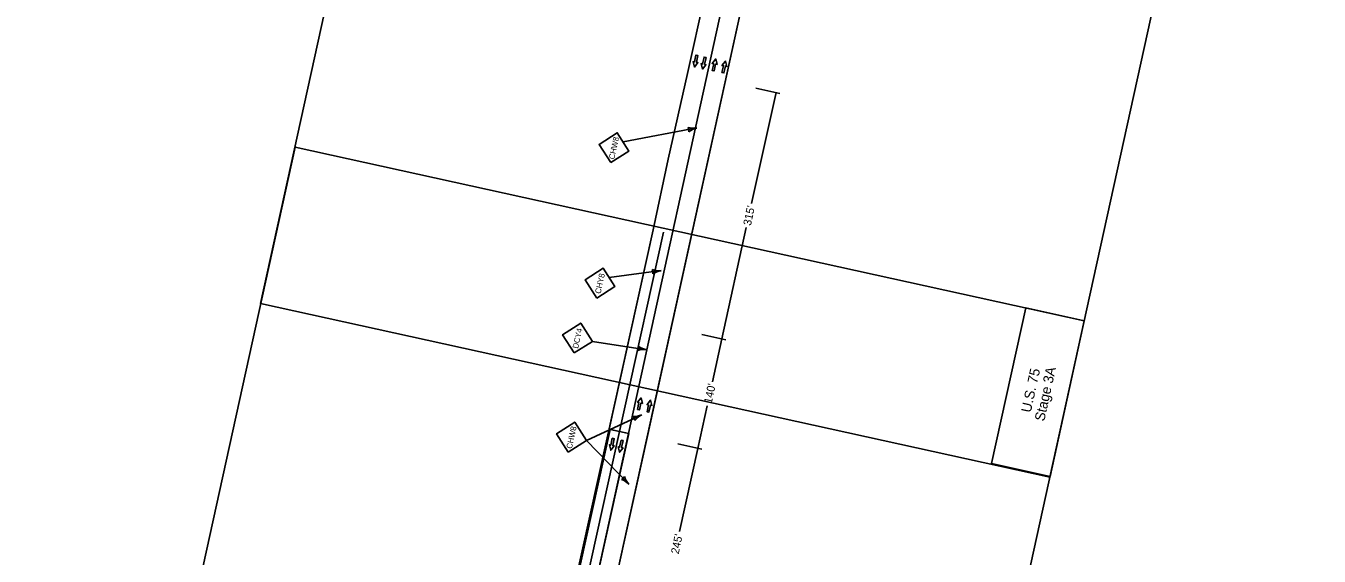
# Model space of a CAD drawing. Extents: x 14104283 to 14129344, y 8637090 to 8673339.
# Drawn here: x 14106925 to 14108541, y 8638327 to 8638989 of the extents above; entities that cross this region are included whole.
import ezdxf

# ---------------------------------------------------------------- set-up
doc = ezdxf.new("R2010")
doc.units = 0
for name, color, linetype in [('Cell', 7, 'Continuous'), ('Default', 7, 'Continuous'), ('dsnNonPlotable', 7, 'Continuous'), ('dsnPaintExistingBrokenLaneLineWhite', 7, 'Continuous'), ('dsnPaintExistingDoubleCenterYellow', 7, 'Continuous'), ('dsnPaintExistingEdgeLineRightWhite', 7, 'Continuous'), ('dsnStdLabel', 7, 'Continuous'), ('dsnTextOverlapOdd', 7, 'Continuous'), ('EdgePaved', 7, 'Continuous')]:
    doc.layers.add(name, color=color, linetype=linetype)

msp = doc.modelspace()

# ---------------------------------------------------------------- linework, layer by layer
at = {"layer": 'Cell'}
for points in [[(14107762.5, 8638952.7), (14107764.9, 8638952.2), (14107763.1, 8638943.7), (14107764.9, 8638943.3), (14107760.5, 8638937.8), (14107758.8, 8638944.6), (14107760.6, 8638944.2)], [(14107772.6, 8638950.2), (14107775.1, 8638949.7), (14107773.2, 8638941.1), (14107775, 8638940.7), (14107770.7, 8638935.3), (14107768.9, 8638942.1), (14107770.8, 8638941.7)], [(14107785.1, 8638933), (14107782.7, 8638933.5), (14107784.6, 8638942), (14107782.7, 8638942.4), (14107787.1, 8638947.9), (14107788.8, 8638941.1), (14107787, 8638941.5)], [(14107797.4, 8638930.4), (14107795, 8638931), (14107796.9, 8638939.5), (14107795, 8638939.9), (14107799.4, 8638945.3), (14107801.1, 8638938.6), (14107799.3, 8638939)], [(14107691.8, 8638509.5), (14107689.4, 8638510.1), (14107691.2, 8638518.6), (14107689.4, 8638519), (14107693.8, 8638524.5), (14107695.5, 8638517.7), (14107693.7, 8638518.1)], [(14107703.7, 8638506.8), (14107701.3, 8638507.3), (14107703.1, 8638515.8), (14107701.3, 8638516.2), (14107705.7, 8638521.7), (14107707.4, 8638514.9), (14107705.6, 8638515.3)], [(14107657.9, 8638474.1), (14107660.4, 8638473.5), (14107658.5, 8638465), (14107660.3, 8638464.6), (14107655.9, 8638459.1), (14107654.2, 8638465.9), (14107656, 8638465.5)], [(14107669, 8638471.6), (14107671.4, 8638471.1), (14107669.5, 8638462.5), (14107671.4, 8638462.1), (14107667, 8638456.7), (14107665.3, 8638463.5), (14107667.1, 8638463.1)]]:
    msp.add_lwpolyline(points, close=True, dxfattribs=at)
for points in [[(14107760.6, 8638944.2), (14107758.8, 8638944.6), (14107760.5, 8638937.8), (14107764.9, 8638943.3), (14107763.1, 8638943.7), (14107764.9, 8638952.2), (14107762.5, 8638952.7), (14107760.6, 8638944.2)], [(14107770.8, 8638941.7), (14107768.9, 8638942.1), (14107770.7, 8638935.3), (14107775, 8638940.7), (14107773.2, 8638941.1), (14107775.1, 8638949.7), (14107772.6, 8638950.2), (14107770.8, 8638941.7)], [(14107787, 8638941.5), (14107788.8, 8638941.1), (14107787.1, 8638947.9), (14107782.7, 8638942.4), (14107784.6, 8638942), (14107782.7, 8638933.5), (14107785.1, 8638933), (14107787, 8638941.5)], [(14107799.3, 8638939), (14107801.1, 8638938.6), (14107799.4, 8638945.3), (14107795, 8638939.9), (14107796.9, 8638939.5), (14107795, 8638931), (14107797.4, 8638930.4), (14107799.3, 8638939)], [(14107693.7, 8638518.1), (14107695.5, 8638517.7), (14107693.8, 8638524.5), (14107689.4, 8638519), (14107691.2, 8638518.6), (14107689.4, 8638510.1), (14107691.8, 8638509.5), (14107693.7, 8638518.1)], [(14107705.6, 8638515.3), (14107707.4, 8638514.9), (14107705.7, 8638521.7), (14107701.3, 8638516.2), (14107703.1, 8638515.8), (14107701.3, 8638507.3), (14107703.7, 8638506.8), (14107705.6, 8638515.3)], [(14107656, 8638465.5), (14107654.2, 8638465.9), (14107655.9, 8638459.1), (14107660.3, 8638464.6), (14107658.5, 8638465), (14107660.4, 8638473.5), (14107657.9, 8638474.1), (14107656, 8638465.5)], [(14107667.1, 8638463.1), (14107665.3, 8638463.5), (14107667, 8638456.7), (14107671.4, 8638462.1), (14107669.5, 8638462.5), (14107671.4, 8638471.1), (14107669, 8638471.6), (14107667.1, 8638463.1)]]:
    msp.add_lwpolyline(points, dxfattribs=at)
at = {"layer": 'Default'}
for p, q in [((14107678, 8638480.1), (14107872.9, 8639367.3)), ((14107896.3, 8639362.1), (14107701.4, 8638474.9)), ((14107781.5, 8639063.2), (14107752, 8638929.7)), ((14107678, 8638480.1), (14107804.9, 8639058.1)), ((14107708.9, 8638734.4), (14107653.9, 8638485.4)), ((14107625.5, 8638241.2), (14107678, 8638480.1)), ((14107653.9, 8638485.4), (14107678, 8638480.1)), ((14107701.4, 8638474.9), (14107648.9, 8638236.1))]:
    msp.add_line(p, q, dxfattribs=at)
msp.add_lwpolyline([(14107752, 8638929.7), (14107727.7, 8638822.9), (14107708.9, 8638734.4)], dxfattribs=at)
msp.add_lwpolyline([(14107392.9, 8637186.7), (14107369.5, 8637191.9), (14107655.1, 8638485.1), (14107678.5, 8638480)], close=True, dxfattribs=at)
at = {"layer": 'dsnNonPlotable'}
for points in [[(14107218.4, 8638642.3), (14107554.8, 8640173.3), (14108541.3, 8639956.6), (14108204.9, 8638425.6)], [(14106925, 8637306.7), (14107261.4, 8638837.7), (14108247.8, 8638620.9), (14107911.4, 8637089.9)]]:
    msp.add_lwpolyline(points, close=True, dxfattribs=at)
at = {"layer": 'dsnPaintExistingBrokenLaneLineWhite'}
msp.add_line((14107381.2, 8637189.3), (14107721.8, 8638731.5), dxfattribs=at)
at = {"layer": 'dsnPaintExistingDoubleCenterYellow'}
msp.add_line((14107435.8, 8637377.6), (14107678, 8638480.1), dxfattribs=at)
at = {"layer": 'dsnPaintExistingEdgeLineRightWhite'}
for p, q in [((14107781.7, 8639064), (14107752, 8638929.7)), ((14107468.8, 8637416), (14107828.5, 8639053.6)), ((14107708.9, 8638734.4), (14107415.9, 8637407.6))]:
    msp.add_line(p, q, dxfattribs=at)
msp.add_lwpolyline([(14107752, 8638929.7), (14107727.7, 8638822.9), (14107708.9, 8638734.4)], dxfattribs=at)
at = {"layer": 'dsnStdLabel'}
for p, q in [((14107832, 8638767.2), (14107862.5, 8638905.9)), ((14107867.4, 8638904.8), (14107837.3, 8638911.4)), ((14107671.3, 8638844.3), (14107763.6, 8638861.7)), ((14107794.9, 8638598.2), (14107825.4, 8638737.2)), ((14107653.9, 8638675.1), (14107719.1, 8638683.5)), ((14107633.1, 8638595.1), (14107700.8, 8638584.7)), ((14107799.8, 8638597.1), (14107769.7, 8638603.7)), ((14107783.1, 8638544.5), (14107794.9, 8638598.2)), ((14107764.9, 8638461.4), (14107776.5, 8638514.6)), ((14107625.5, 8638471.5), (14107694.7, 8638503.4)), ((14107625.5, 8638471.5), (14107678.6, 8638416.6)), ((14107769.8, 8638460.4), (14107739.6, 8638467)), ((14107742, 8638357.5), (14107764.9, 8638461.4))]:
    msp.add_line(p, q, dxfattribs=at)
for points in [[(14107655.9, 8638818.4), (14107678.6, 8638832.9), (14107664.1, 8638855.7), (14107641.3, 8638841.1)], [(14107638.4, 8638649.1), (14107661.1, 8638663.7), (14107646.6, 8638686.4), (14107623.9, 8638671.9)], [(14107610.3, 8638580.6), (14107633.1, 8638595.1), (14107618.5, 8638617.9), (14107595.8, 8638603.3)], [(14107602.8, 8638456.9), (14107625.5, 8638471.5), (14107611, 8638494.2), (14107588.2, 8638479.7)]]:
    msp.add_lwpolyline(points, close=True, dxfattribs=at)
for centre, radius, start, end in [((14107759.4, 8638884.2), 22.9, 252.5977, 280.669), ((14107744.7, 8638858.1), 8.86, 352.9347, 28.4031), ((14107767.9, 8638839.1), 22.9, 100.6688, 128.7401), ((14107716, 8638706.2), 22.9, 249.1268, 277.1981), ((14107699.8, 8638681), 8.86, 349.4638, 24.9322), ((14107721.8, 8638660.6), 22.9, 97.1979, 125.2692), ((14107681.8, 8638587.7), 8.86, 333.54, 9.0085), ((14107697.3, 8638562.1), 22.9, 81.2742, 109.3455), ((14107704.3, 8638607.4), 22.9, 233.203, 261.2743), ((14107685.1, 8638524.3), 22.9, 266.7252, 294.7965), ((14107677.3, 8638495.4), 8.86, 7.0622, 42.5306), ((14107704.4, 8638482.6), 22.9, 114.7963, 142.8676), ((14107665.6, 8638430.8), 8.86, 294.5639, 330.0324), ((14107661.6, 8638401.1), 22.9, 42.2981, 70.3694), ((14107695.5, 8638432), 22.9, 194.227, 222.2983)]:
    msp.add_arc(centre, radius, start, end, dxfattribs=at)
at = {"layer": 'dsnTextOverlapOdd'}
for points in [[(14108247.8, 8638620.9), (14108205.1, 8638426.3), (14108131.8, 8638442.4), (14108174.6, 8638637)], [(14108131.8, 8638442.4), (14108174.6, 8638637), (14108247.8, 8638620.9), (14108205.1, 8638426.3)]]:
    msp.add_lwpolyline(points, close=True, dxfattribs=at)
at = {"layer": 'EdgePaved'}
msp.add_line((14107872.9, 8639367.3), (14107678, 8638480.1), dxfattribs=at)

# ---------------------------------------------------------------- texts
at = {"layer": 'dsnStdLabel'}
for s, height, rotation, p in [('CHW8', 7.2, 77.6078, (14107660.4, 8638822)), ("315'", 10, 78.0531, (14107831.1, 8638739.1)), ('CHY8', 7.2, 77.6078, (14107643.2, 8638654.1)), ('DCY4', 7.2, 77.6078, (14107615.1, 8638585.6)), ("140'", 10, 78.0531, (14107782.1, 8638516.8)), ('CHW8', 7.2, 77.6078, (14107607.3, 8638460.5)), ("245'", 10, 78.0531, (14107740.8, 8638328.8))]:
    msp.add_text(s, height=height, rotation=rotation, dxfattribs=at).set_placement(p)
at = {"layer": 'dsnTextOverlapOdd'}
for s, p in [('U.S. 75', (14108180.8, 8638505.4)), ('Stage 3A', (14108197.7, 8638494.6))]:
    msp.add_text(s, height=12.5, rotation=77.6078, dxfattribs=at).set_placement(p)

doc.saveas('drawing.dxf')
